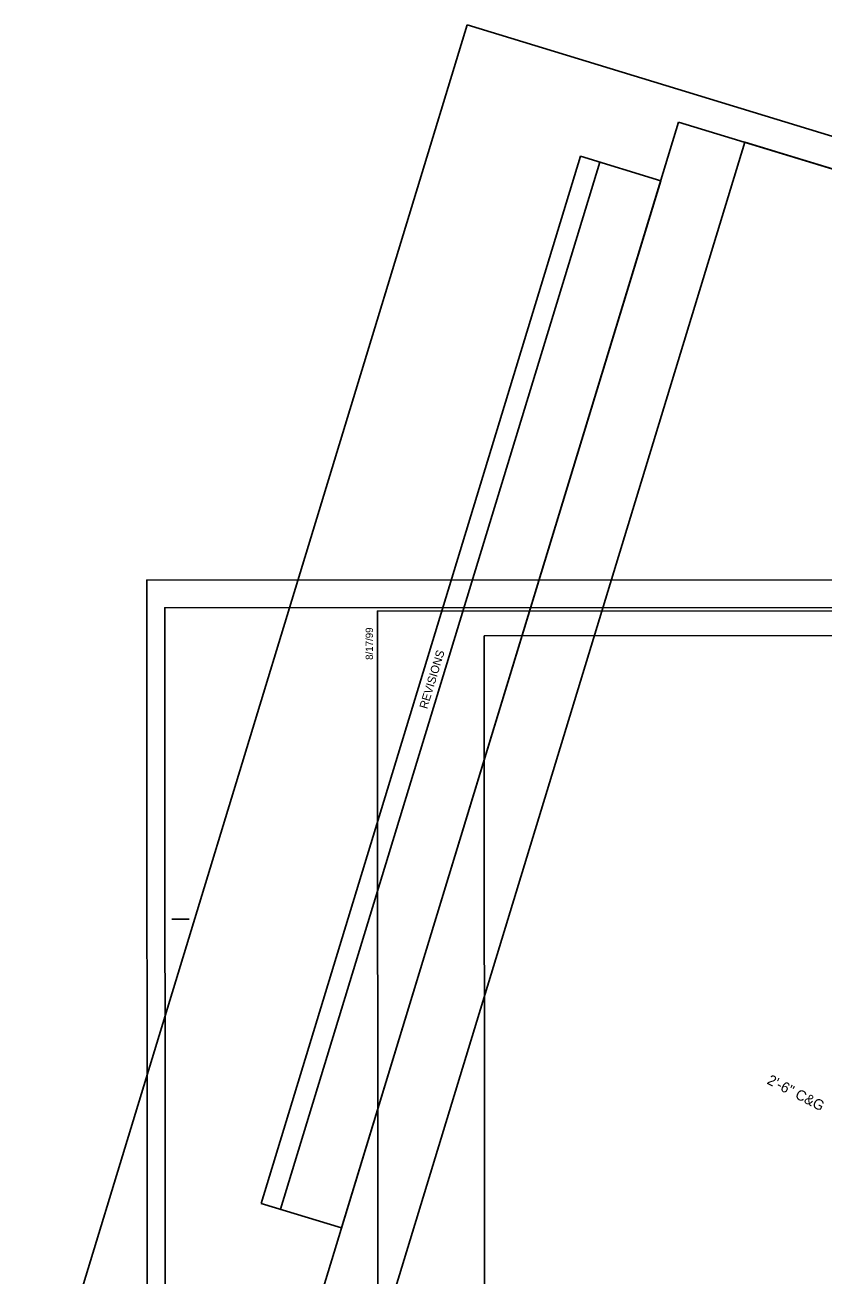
# Model space of a CAD drawing. Extents: x 1443477 to 1619989, y 756574 to 899826.
# Drawn here: x 1619192.2 to 1619422.9, y 898058.9 to 898420 of the extents above; entities that cross this region are included whole.
import ezdxf

# ---------------------------------------------------------------- set-up
doc = ezdxf.new("R2010")
doc.units = 0
for name, color, linetype in [('Default', 7, 'Continuous'), ('Prop Dimension', 7, 'Continuous'), ('Sheet Block Revision CELL', 7, 'Continuous'), ('Sheet Clip Boundary CELL', 7, 'Continuous'), ('Sheet Cutting Line CELL', 7, 'Continuous'), ('Sheet Layout Plan Border', 7, 'Continuous'), ('Sheet Plan CELL', 7, 'Continuous'), ('Sheet Plan Layout CELL', 7, 'Continuous'), ('Sheet Plot Border Inside CELL', 7, 'Continuous'), ('Sheet Plot Border Outside CELL', 7, 'Continuous')]:
    doc.layers.add(name, color=color, linetype=linetype)

msp = doc.modelspace()

# ---------------------------------------------------------------- linework, layer by layer
at = {"layer": 'Default'}
msp.add_lwpolyline([(1619324.8, 898243.59), (1619813.94, 898243.79), (1619813.98, 898167.39), (1619859.81, 898167.41), (1619859.94, 897863.4), (1619324.96, 897863.18)], close=True, dxfattribs=at)
at = {"layer": 'Sheet Block Revision CELL'}
msp.add_line((1619265.99, 898077.89), (1619358.19, 898380.41), dxfattribs=at)
msp.add_lwpolyline([(1619260.42, 898079.58), (1619352.63, 898382.1), (1619375.79, 898375.05), (1619283.59, 898072.53)], close=True, dxfattribs=at)
at = {"layer": 'Sheet Clip Boundary CELL'}
msp.add_lwpolyline([(1619277.64, 897984.43), (1619813.32, 897821.17), (1619911.11, 898142), (1619838.69, 898164.07), (1619863.35, 898244.99), (1619400.09, 898386.19)], close=True, dxfattribs=at)
at = {"layer": 'Sheet Cutting Line CELL'}
for p, q in [((1619319.88, 898420.04), (1619192.19, 898001.07)), ((1619964.03, 898223.71), (1619319.88, 898420.04))]:
    msp.add_line(p, q, dxfattribs=at)
at = {"layer": 'Sheet Layout Plan Border'}
msp.add_lwpolyline([(1619277.64, 897984.43), (1619813.32, 897821.17), (1619911.11, 898142), (1619838.69, 898164.07), (1619863.35, 898244.99), (1619400.09, 898386.19)], close=True, dxfattribs=at)
at = {"layer": 'Sheet Plan CELL'}
for p, q in [((1619293.95, 898250.71), (1619293.95, 898250.71)), ((1619234.59, 898161.68), (1619239.6, 898161.69))]:
    msp.add_line(p, q, dxfattribs=at)
for points in [[(1619294.13, 897830.71), (1619293.94, 898250.7), (1619813.94, 898250.93), (1619813.97, 898190.91), (1619893.98, 898190.94), (1619894.13, 897830.96)], [(1619893.97, 898250.96), (1619293.95, 898250.71), (1619294.13, 897830.71), (1619894.13, 897830.96)]]:
    msp.add_lwpolyline(points, close=True, dxfattribs=at)
at = {"layer": 'Sheet Plan Layout CELL'}
msp.add_lwpolyline([(1619380.95, 898392.01), (1619258.51, 897990.27), (1619832.45, 897815.34), (1619930.23, 898136.17), (1619838.69, 898164.07), (1619863.35, 898244.99)], close=True, dxfattribs=at)
at = {"layer": 'Sheet Plot Border Inside CELL'}
msp.add_lwpolyline([(1619232.74, 897829.68), (1619899.13, 897829.97), (1619898.96, 898251.96), (1619232.56, 898251.68)], close=True, dxfattribs=at)
at = {"layer": 'Sheet Plot Border Outside CELL'}
msp.add_lwpolyline([(1619227.54, 897821.68), (1619900.94, 897821.96), (1619900.76, 898259.96), (1619227.36, 898259.68)], close=True, dxfattribs=at)

# ---------------------------------------------------------------- texts
at = {"layer": 'Prop Dimension'}
msp.add_text('2\'-6" C&G', height=3, rotation=332.8822, dxfattribs=at).set_placement((1619406.23, 898114.28))
at = {"layer": 'Sheet Block Revision CELL'}
msp.add_text('REVISIONS', height=2.4, rotation=73.0495, dxfattribs=at).set_placement((1619308.31, 898222.29))
at = {"layer": 'Sheet Plan CELL'}
msp.add_text('8/17/99', height=2.1, rotation=90.0239, dxfattribs=at).set_placement((1619292.67, 898236.62))

doc.saveas('drawing.dxf')
